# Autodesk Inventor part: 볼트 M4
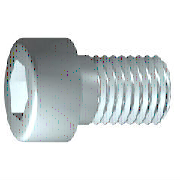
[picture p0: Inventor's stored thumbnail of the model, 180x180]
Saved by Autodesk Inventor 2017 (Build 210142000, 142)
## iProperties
IsCustomPart: 1
Created: 2012-02
Part Number: 볼트 M4
Material: 스테인리스강
Description: 6각 소켓 머리 캡 나사
Document SubType Name: Modeling
Standard: ISO 4762
Designer: mduedu
Standard Revision: Fourth edition 2004-03-01
Standards Organization: ISO
Language: ko-KR
Size Designation: M4 x 10
Categories: <MemberInstance><Categories><Category DisplayName="조임쇠" InternalName="e4da775c-781d-43d5-af7c-5136215cf5a6" Mnemonic="FSTN"><Category DisplayName="볼트" InternalN
Density: 8.08 g/cm^3
Mass: 2.0939 g
Surface Area: 3.06255 cm^2
Volume: 0.259146 cm^3
Appearance: 반광택
Author: mduedu
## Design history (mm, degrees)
sketch "스케치1"
  geometry: L1 (-1, 0)-(10, 0); L2 (10, 0)-(10, 2); L3 (10, 2)-(1.75, 2); L4 (1.75, 2)-(1.32, 2); L5 (1.32, 2)-(0, 2); L6 (0, 2)-(0, 3.5); L7 (0, 3.5)-(-4, 3.5); L8 (-4, 3.5)-(-4, 1.732); L9 (-4, 1.732)-(-2, 1.732); L10 (-2, 1.732)-(-1, 0); L11 (-6.8, 0)-(12.8, 0) reference; L12 (0, -0.7)-(0, 4.2) reference; L13 (1.75, 2)-(0, 2)
  constraints: 22 end point, 6 parallel, 2 collinear, 2 perpendicular, 1 horizontal, 1 point on line
  dimensions: "d1" = 8.25 distance from line of L3.end L2 (= GEL); "d2" = 0.42952 distance of L4.end L3.end (computed from GAL); "d3" = 4 distance between parallel lines of L8 L6 (= KOH); "d4" = 2 distance of L8.end L9.end (= INTI); "d5" = 60 deg angle of L10 L1; "d6" = 4 diameter of L3 L1 (= GD); "d7" = 4 diameter of L5 L1 (= BDM); "d8" = 3.4641 diameter of L9 L1 (= 1.1547 x SW); "d9" = 7 diameter of L7 L1 (= KOD); "d26" = 10 distance between parallel lines of L12 L2 (= NLG)
revolve "본체" sketch "스케치1" stored, may be unused: angle "d10" = 90 deg
sketch "스케치2"
  geometry: L1 (0, -4.9)-(0, 4.9) reference; L2 (-4.9, 0)-(4.9, 0) reference; L3 (1.732, 0)-(0.866, -1.5); L4 (0.866, -1.5)-(-0.866, -1.5); L5 (-0.866, -1.5)-(-1.732, 0); L6 (-1.732, 0)-(-0.866, 1.5); L7 (-0.866, 1.5)-(0.866, 1.5); L8 (0.866, 1.5)-(1.732, 0); 2 further points
  constraints: 12 end point, 1 coincident, 1 horizontal alignment, 1 point on line, 12 other
extrude "슬롯" join sketch "스케치2" stored distance "d11" = 10; taper "d12" = 0 deg
workplane "Work Plane1"
body "Solid1"
fillet "모깎기1" dims "d17" = 0.4 (= RR)
feature "스레드" dims "d13" = 8.25 (= GEL), "d14" = 0
chamfer "모따기1" distance "d15" = 0.42941 (= -0.5 x SPD + 0.5 x GD); stored, may be unused: second distance "d16" = 0.42941 (= GUL), angle "d27" = 45 deg
other parameters: "GD" = 4 [user parameter; used in 2 equation terms], "NLG" = 10 [user parameter; used in 1 equation term], "GEL" = 8.25 [user parameter; used in 2 equation terms], "KOD" = 7 [user parameter; used in 1 equation term], "KOH" = 4 [user parameter; used in 1 equation term], "INTI" = 2 [user parameter; used in 1 equation term], "GAL" = 0.42941 (= 0.61345 x PTC) [user parameter; used in 1 equation term], "GUL" = 0.42941 (= 0.61345 x PTC) [user parameter; used in 1 equation term], "BDM" = 4 (= NND) [user parameter; used in 1 equation term], "SW" = 3 [user parameter; used in 2 equation terms], "RR" = 0.4 [user parameter; used in 1 equation term], "SPD" = 3.14117 (= NND - 1.2269 x PTC) [user parameter; used in 1 equation term], "d19" = 0, "d28" = 0, "d29" = 0, "R" = 0.1 [user parameter], "TOA" = 30 deg [user parameter], "GD1" = 3.14117 (= THREADDIA - 1.2269 x PTC) [user parameter], "THREADDIA" = 4 [user parameter; used in 1 equation term], "FAWI" = 45 deg [user parameter], "TPU" = 14.28571 (computed from PTC) [user parameter], "PTC" = 0.7 [user parameter; used in 5 equation terms], "NND" = 4 [user parameter; used in 2 equation terms], "E0" = 3.465 (= 1.155 x SW) [user parameter]
